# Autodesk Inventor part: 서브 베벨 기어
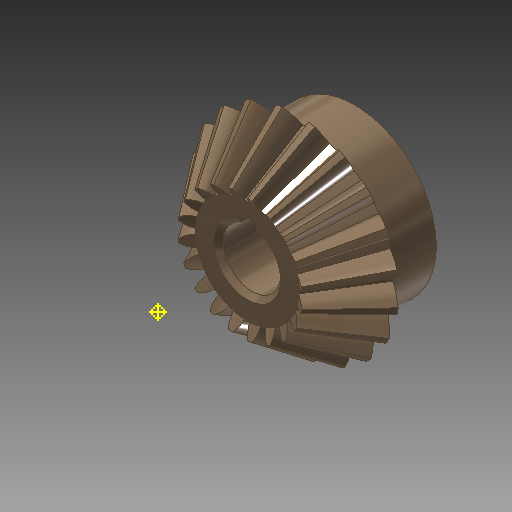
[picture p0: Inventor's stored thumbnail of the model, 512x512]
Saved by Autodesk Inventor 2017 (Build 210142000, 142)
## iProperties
Created: 2016-04
Part Number: 서브 베벨 기어
Material: 강철, 탄소
Document SubType Name: Modeling
Designer: mdu
Categories: <?xml version="1.0" encoding="UTF-16"?> <MemberInstance><Categories><FamilyTemplate><FamilyTemplateParameter ValueType="xs:double" Id="1" ObjectReferenceKey="da
Mass: 135.037 g
Surface Area: 63.6518 cm^2
Volume: 17.1585 cm^3
Density: 7.87 g/cm^3
Appearance: 얼룩무늬
CustomPartVersion: 1
Author: mdu
Revision Number: 1
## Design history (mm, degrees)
node "맨 위 점"
node "메쉬 평면2"
sketch "톱니 본체 스케치"
  geometry: L1 (0, 0)-(18.003, -31.331); L2 (18.003, -31.331)-(21.664, -28.891); L3 (21.664, -28.891)-(0, 0); L4 (20, -30)-(0, 0); L5 (10.813, -18.818)-(13.012, -17.352); L6 (18.003, -31.331)-(10.813, -18.818); L7 (21.664, -28.891)-(13.012, -17.352); L8 (0, -39.387)-(0, 6.564) reference; L9 (0, -30)-(21.664, -30)
  constraints: 16 end point, 4 point on line, 3 perpendicular, 2 collinear, 1 horizontal alignment, 1 vertical alignment
  dimensions: "d0" = 40 diameter of L4.start L8 (= da_de); "d1" = 36.00616 diameter of L1.end L8 (= da_dfe); "d2" = 43.3282 diameter of L2.end L8 (= da_dae); "d3" = 14.4 distance between parallel lines of L2 L5 (= da_b); "d4" = 28.8906 vertical distance of L2.end L1.start (= da_ve)
revolve "톱니 본체" sketch "톱니 본체 스케치" stored, may be unused: angle "d5" = 90 deg
node "시작점"
node "톱니 평면"
sketch "시작 스케치"
  geometry: L1 (0, -23.505)-(0, 10.645) reference; L2 (-0.834, -2.928)-(0.834, -2.928); A1 r 8.898 centre (-9.698, -3.713) between (-0.834, -2.928) and (-3.903, 3.04); A2 r 8.898 centre (9.698, -3.713) between (3.903, 3.04) and (0.834, -2.928); A3 r 27.357 centre (0, -24.037) between (3.903, 3.04) and (-3.903, 3.04); 1 further point
  constraints: 6 point on circle, 3 centre point, 3 symmetric about line, 2 end point, 1 coincident, 1 perpendicular, 1 other
  dimensions: "d7" = 8.89846 radius of A1 (= fd_rr); "d8" = 9.69794 horizontal distance of point (0, -24.037) A1.centre (= fd_x); "d9" = 20.32439 vertical distance of point (0, -24.037) A1.centre (= fd_y); "d57" = 27.35701 radius of A3 (= 0.5 x fd_dva + 0.3 x da_he); "d58" = 21.10901 distance from line of A3.centre L2 (= 0.5 x fd_dva - 1.12 x da_he)
node "끝점"
  node "끝 평면"
sketch "3D 스케치 오른쪽"
  node "Helical Curve Right" dims "d65" = 229.90621 (computed from da_dm, da_delta, da_beta), "d66" = 31.5, "d67" = 40 (= da_de), "d68" = -5.88003 (= -da_delta), "d69" = 12.16458 (computed from fd_loft, da_delta)
node "끝 평면 오른쪽"
sketch "끝 스케치 오른쪽"
  geometry: L1 (0, -22.649)-(0, 12.15) reference; L2 (-0.497, -1.72)-(0.497, -1.72); A1 r 5.299 centre (-5.775, -2.187) between (-0.497, -1.72) and (-2.324, 1.834); A2 r 5.299 centre (5.775, -2.187) between (2.324, 1.834) and (0.497, -1.72); A3 r 16.291 centre (0, -14.29) between (2.324, 1.834) and (-2.324, 1.834); 1 further point
  constraints: 6 point on circle, 3 centre point, 3 symmetric about line, 2 end point, 1 coincident, 1 perpendicular, 1 other
  dimensions: "d70" = 5.77526 horizontal distance of A3.centre A1.centre (computed from fd_x, fd_ratio); "d71" = 12.10346 vertical distance of point (0, -14.29) A1.centre (computed from fd_y, fd_ratio); "d72" = 5.29916 radius of A1 (computed from fd_rr, fd_ratio); "d73" = 12.57071 distance from line of point (0, -14.29) L2 (computed from d58, fd_ratio); "d74" = 16.29149 radius of A3 (computed from d57, fd_ratio)
feature "로프트 오른쪽" sketch "끝 스케치 오른쪽" dims "d75" = 0, "d77" = 0, "d79" = 0, "d80" = 90 deg, "d85" = 20, "d92" = 90 deg, "d93" = 90 deg, "da_teethtype" = 0 [user parameter]
sketch "3D 스케치 왼쪽"
  node "Helical Curve Left" dims "d26" = 229.90621 (computed from da_dm, da_delta, da_beta), "d27" = 12.16458 (computed from fd_loft, da_delta), "d28" = 40 (= da_de), "d29" = -5.88003 (= -da_delta)
node "끝 평면 왼쪽"
sketch "끝 스케치 왼쪽" dims "d56" = 10.82768 (derived)
  geometry: L1 (0, -35.087)-(0, 18.089) reference; L2 (-0.497, -1.716)-(0.497, -1.716); A1 r 5.299 centre (-5.775, -2.183) between (-0.497, -1.716) and (-2.324, 1.838); A2 r 5.299 centre (5.775, -2.183) between (2.324, 1.838) and (0.497, -1.716); A3 r 16.291 centre (0, -14.287) between (2.324, 1.838) and (-2.324, 1.838); 2 further points; 1 other entity
  constraints: 6 point on circle, 3 centre point, 3 symmetric about line, 2 end point, 1 coincident, 2 other
  dimensions: "d30" = 5.29916 radius of A1 (computed from fd_rr, fd_ratio); "d31" = 5.77526 horizontal distance of point (0, -14.287) A1.centre (computed from fd_x, fd_ratio); "d32" = 12.10346 vertical distance of A1.centre point (0, -14.287) (computed from fd_y, fd_ratio); "d61" = 16.29149 radius of A3 (computed from d57, fd_ratio); "d62" = 12.57071 distance from line of point (0, -14.287) L2 (computed from d58, fd_ratio)
feature "로프트 왼쪽" sketch "끝 스케치 왼쪽" dims "d35" = 0, "d37" = 0, "d39" = 0, "d40" = 90 deg, "d84" = 10, "d90" = 90 deg, "d91" = 90 deg, "da_teethtype" = 0 [user parameter]
sketch "본체 스케치"
  geometry: L1 (0, -35.038)-(0, -19.531) reference; L2 (18.003, -31.331)-(10.813, -18.818) reference; L3 (10.813, -18.818)-(0, -18.818); L4 (18.003, -31.331)-(0, -31.331)
  constraints: 4 end point, 2 perpendicular, 2 point on line
revolve "본체 고정" sketch "본체 스케치" stored, may be unused: angle "d46" = 90 deg
feature "피치 지름" dims angle "d47" = 90 deg
sketch "스케치8"
  geometry: C1 r 17 at (0, 0); 1 further point
  constraints: 1 centre point, 1 coincident
  dimensions: "d94" = 34 diameter of C1
extrude "돌출1" join sketch "스케치8" distance "d95" = 10; taper "d96" = 0 deg
sketch "스케치9"
  geometry: 1 further point
hole "구멍1" sketch "스케치9" at (0, 0) diameter "d97" = 12; stored, may be unused: countersink angle "d101" = 90 deg, drill point angle "d103" = 118 deg; dims "d98" = 6, "d99" = 4, "d100" = 2, "d102" = 8
sketch "스케치10"
  geometry: 1 further point
sketch "스케치11"
  geometry: 1 further point
sketch "스케치12"
  geometry: L1 (-2, 5.657)-(-2, 7.8); L2 (-2, 7.8)-(2, 7.8); L3 (2, 7.8)-(2, 5.657); A1 r 6 centre (0, 0) between (-2, 5.657) and (2, 5.657) reference; 1 further point
  constraints: 6 end point, 2 parallel, 2 point on circle, 1 perpendicular, 1 vertical
  dimensions: "d104" = 4 distance of L1.end L2.end; "d105" = 13.8 dimension on A1 L2
extrude "돌출2" cut sketch "스케치12" stored distance "d106" = 7; taper "d107" = 0 deg
chamfer "모따기1" distance "d108" = 1; stored, may be unused: second distance "d109" = 2, angle "d110" = 45 deg
body "Solid1"
feature "로프트" dims "d17" = 0, "d18" = 90 deg, "d19" = 0, "d20" = 90 deg, "d89" = 0, "da_teethtype" = 0 [user parameter]
pattern_circular "원형 패턴" dims angle "d22" = 360 deg, "d88" = 0, "da_teethtype" = 0 [user parameter]
pattern_circular "원형 패턴 오른쪽" dims angle "d82" = 360 deg, "da_teethtype" = 0 [user parameter]
pattern_circular "원형 패턴 왼쪽" dims angle "d42" = 360 deg, "da_teethtype" = 0 [user parameter]
sketch "끝 스케치"
  geometry: L1 (0, -15.359)-(0, 6.983) reference; L2 (-0.497, -1.72)-(0.497, -1.72); A1 r 5.299 centre (-5.775, -2.187) between (-0.497, -1.72) and (-2.324, 1.834); A2 r 5.299 centre (5.775, -2.187) between (2.324, 1.834) and (0.497, -1.72); A3 r 16.291 centre (0, -14.29) between (2.324, 1.834) and (-2.324, 1.834); 1 further point
  constraints: 6 point on circle, 3 centre point, 3 symmetric about line, 2 end point, 1 coincident, 1 other
  dimensions: "d12" = 5.29916 radius of A1 (computed from fd_rr, fd_ratio); "d15" = 5.77526 horizontal distance of A1.centre point (0, -14.29) (computed from fd_x, fd_ratio); "d16" = 12.10346 vertical distance of A1.centre point (0, -14.29) (computed from fd_y, fd_ratio); "d59" = 16.29149 radius of A3 (computed from d57, fd_ratio); "d60" = 12.57071 distance from line of A3.centre L2 (computed from d58, fd_ratio)
sketch "Sketch6"
  geometry: L1 (20, -30)-(0, 0) reference; L2 (0, -37.8)-(0, 6.3) reference
body "Srf1"
other parameters: "da_b" = 14.4 [user parameter; used in 2 equation terms], "da_de" = 40 [user parameter; used in 4 equation terms], "da_dae" = 43.3282 [user parameter; used in 2 equation terms], "da_dfe" = 36.00616 [user parameter; used in 1 equation term], "da_le" = 36.05551 [user parameter; used in 1 equation term], "da_omega" = 90 deg [user parameter; used in 1 equation term], "da_beta" = 0 [user parameter; used in 2 equation terms], "da_delta" = 5.88003 [user parameter; used in 8 equation terms], "da_alpha" = 20 deg [user parameter; used in 2 equation terms], "da_he" = 4.4 [user parameter; used in 4 equation terms], "da_ve" = 28.8906 [user parameter; used in 1 equation term], "fd_dv" = 48.07402 (computed from da_de, da_delta) [user parameter; used in 1 equation term], "fd_dva" = 52.07402 (computed from da_dae, da_delta) [user parameter; used in 3 equation terms], "fd_dvb" = 45.1748 (computed from fd_dv, da_alpha) [user parameter; used in 2 equation terms], "da_zv" = 240.37008 [user parameter; used in 1 equation term], "fd_loft" = 14.62 (= da_b + 0.05 x da_he) [user parameter; used in 4 equation terms], "fd_ratio" = 5.95514 (computed from da_le, fd_loft) [user parameter; used in 15 equation terms], "fd_rr" = 8.89846 (computed from fd_dd, fd_dvb) [user parameter; used in 6 equation terms], "fd_angle" = 0.66075 (computed from da_zv) [user parameter; used in 4 equation terms], "fd_x1" = 1.58709 (computed from da_dvw, fd_angle) [user parameter; used in 1 equation term], "fd_y1" = 23.98456 (computed from da_dvw, fd_angle) [user parameter; used in 1 equation term], "fd_x2" = 8.11084 (computed from fd_rr, fd_angle2, fd_angle) [user parameter; used in 1 equation term], "fd_y2" = 3.66016 (computed from fd_rr, fd_angle2, fd_angle) [user parameter; used in 1 equation term], "fd_x" = 9.69794 (= fd_x1 + fd_x2) [user parameter; used in 4 equation terms], "fd_y" = 20.32439 (= fd_y1 - fd_y2) [user parameter; used in 4 equation terms], "fd_angle2" = 3.57832 (computed from fd_dvb, fd_dd, da_alpha) [user parameter; used in 2 equation terms], "fd_dd" = 48.55402 (= fd_dva - 0.8 x da_he) [user parameter; used in 2 equation terms], "da_dvw" = 48.07402 [user parameter; used in 2 equation terms], "d11" = 14.62 (= fd_loft), "da_dm" = 32.01232 [user parameter; used in 2 equation terms], "da_x" = 0 [user parameter], "da_m" = 2 [user parameter], "d48" = 0, "d49" = 0, "d50" = 90 deg (= da_omega), "d51" = 9 deg (computed from da_z), "d52" = 0, "d53" = 0, "d54" = 0
